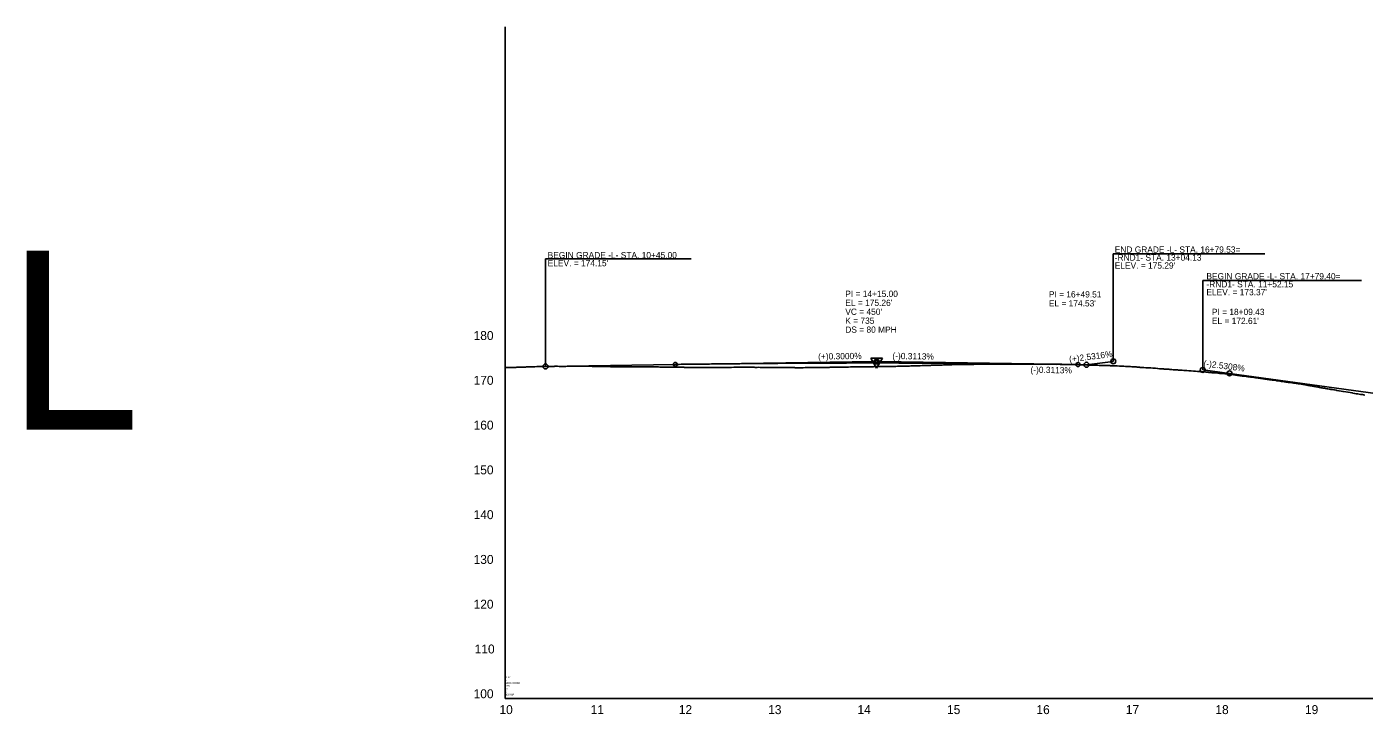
# Model space of a CAD drawing. Extents: x 1778432 to 1784301, y 601022 to 621789.
# Drawn here: x 1779608 to 1781103, y 621022 to 621789 of the extents above; entities that cross this region are included whole.
import ezdxf

# ---------------------------------------------------------------- set-up
doc = ezdxf.new("R2010")
doc.units = 0
for name, color, linetype in [('Exist Profile Cell', 7, 'Continuous'), ('Exist Vertical Profile Ground Line', 7, 'Continuous'), ('Exist Vertical Profile Horizontal Axis Label Major', 7, 'Continuous'), ('Exist Vertical Profile Vertical Axis Label', 7, 'Continuous'), ('Prop PFL Text', 7, 'Continuous'), ('Prop PFL VPI Symbol CELL', 7, 'Continuous'), ('Prop Vertical Profile Curve Label', 7, 'Continuous'), ('Prop Vertical Profile Grade', 7, 'Continuous'), ('Prop Vertical Profile Grade Label', 7, 'Continuous'), ('Prop VPI Label', 7, 'Continuous')]:
    doc.layers.add(name, color=color, linetype=linetype)

msp = doc.modelspace()

# ---------------------------------------------------------------- linework, layer by layer
at = {"layer": 'Exist Profile Cell'}
for q in [(1780143, 621789.2), (1784155.7, 621039.2), (1780143, 621039.2)]:
    msp.add_line((1780143, 621039.2), q, dxfattribs=at)
at = {"layer": 'Exist Vertical Profile Ground Line'}
msp.add_lwpolyline([(1780143, 621408.5), (1780143.6, 621408.6), (1780144.9, 621408.7), (1780145.6, 621408.7), (1780148.1, 621408.8), (1780150.2, 621408.8), (1780150.6, 621408.8), (1780151, 621408.8), (1780153.1, 621408.9), (1780155, 621408.9), (1780155.6, 621409), (1780156.3, 621409), (1780158.1, 621409), (1780158.9, 621409), (1780160.6, 621409.1), (1780162.1, 621409.1), (1780163.1, 621409.1), (1780164.3, 621409.2), (1780165.6, 621409.2), (1780166.8, 621409.3), (1780168.1, 621409.3), (1780169.2, 621409.3), (1780170.6, 621409.4), (1780172.3, 621409.5), (1780173.1, 621409.5), (1780173.9, 621409.5), (1780175.6, 621409.6), (1780176.2, 621409.6), (1780178.1, 621409.7), (1780180.2, 621409.7), (1780180.6, 621409.8), (1780183.3, 621409.8), (1780185.7, 621409.9), (1780186.9, 621409.9), (1780188.1, 621409.9), (1780190.9, 621410), (1780193.1, 621410), (1780195.2, 621410), (1780195.7, 621410), (1780197.5, 621410), (1780198.2, 621410.1), (1780199.9, 621410.1), (1780200.7, 621410.1), (1780201.5, 621410.1), (1780203.2, 621410), (1780204.2, 621410), (1780205.7, 621410), (1780207, 621410), (1780208.2, 621410), (1780209.4, 621410), (1780210.7, 621410), (1780212.2, 621410.1), (1780213.2, 621410.1), (1780214.8, 621410.1), (1780215.7, 621410.1), (1780217.5, 621410.2), (1780218.2, 621410.2), (1780218.8, 621410.2), (1780220.7, 621410.2), (1780221.2, 621410.2), (1780223.2, 621410.2), (1780223.5, 621410.2), (1780225.7, 621410.2), (1780228.2, 621410.2), (1780229.5, 621410.2), (1780230.8, 621410.2), (1780231.1, 621410.2), (1780232.7, 621410.1), (1780233.5, 621410.1), (1780235.7, 621410.1), (1780237.7, 621410.1), (1780238.2, 621410.1), (1780240.1, 621410), (1780240.7, 621410), (1780242.5, 621410), (1780243.2, 621410), (1780244.1, 621410), (1780245.7, 621409.9), (1780246.8, 621409.9), (1780248.2, 621409.9), (1780249.6, 621409.9), (1780250.8, 621409.9), (1780251.9, 621409.9), (1780253.3, 621409.8), (1780254.7, 621409.8), (1780255.8, 621409.7), (1780257.4, 621409.7), (1780258.3, 621409.7), (1780260.1, 621409.7), (1780260.8, 621409.6), (1780262.7, 621409.6), (1780263.3, 621409.6), (1780263.7, 621409.6), (1780265.8, 621409.6), (1780266.1, 621409.6), (1780268.5, 621409.6), (1780270.8, 621409.5), (1780271.7, 621409.5), (1780273.3, 621409.5), (1780275.8, 621409.5), (1780277.9, 621409.4), (1780278.3, 621409.4), (1780280.3, 621409.4), (1780280.8, 621409.4), (1780281.4, 621409.4), (1780283.3, 621409.4), (1780285, 621409.3), (1780285.8, 621409.3), (1780287.4, 621409.3), (1780288.3, 621409.3), (1780289.8, 621409.3), (1780290.8, 621409.3), (1780292, 621409.3), (1780293.3, 621409.3), (1780294.5, 621409.3), (1780295.8, 621409.3), (1780296.9, 621409.3), (1780298.3, 621409.3), (1780299.2, 621409.3), (1780300.8, 621409.3), (1780302.7, 621409.3), (1780303.3, 621409.3), (1780305.3, 621409.3), (1780305.8, 621409.3), (1780308, 621409.3), (1780308.3, 621409.3), (1780308.7, 621409.3), (1780310.9, 621409.3), (1780313.4, 621409.3), (1780314.2, 621409.3), (1780315.9, 621409.2), (1780318.4, 621409.2), (1780320.5, 621409.2), (1780320.9, 621409.2), (1780321.3, 621409.2), (1780323.4, 621409.2), (1780323.9, 621409.2), (1780325.9, 621409.1), (1780326.6, 621409.1), (1780328.4, 621409.1), (1780329.9, 621409.1), (1780330.9, 621409.1), (1780332.3, 621409.1), (1780333.4, 621409.1), (1780334.7, 621409), (1780335.9, 621409), (1780337.1, 621409), (1780338.4, 621409), (1780339.4, 621409), (1780340.9, 621409), (1780342.6, 621409), (1780343.4, 621408.9), (1780344.2, 621408.9), (1780345.9, 621408.9), (1780346.5, 621408.9), (1780348.4, 621408.9), (1780348.9, 621408.9), (1780350.9, 621408.9), (1780353.4, 621408.9), (1780356, 621408.9), (1780356.5, 621408.9), (1780358.6, 621408.9), (1780361.2, 621408.8), (1780363.4, 621408.8), (1780363.9, 621408.8), (1780366, 621408.9), (1780366.5, 621408.9), (1780368.5, 621408.8), (1780370.2, 621408.8), (1780371, 621408.8), (1780372.5, 621408.8), (1780373.5, 621408.8), (1780374.9, 621408.8), (1780376, 621408.8), (1780377.3, 621408.8), (1780378.5, 621408.8), (1780379.6, 621408.8), (1780381, 621408.9), (1780382.5, 621408.9), (1780383.5, 621408.9), (1780385.2, 621408.8), (1780386, 621408.8), (1780386.7, 621408.8), (1780388.5, 621408.9), (1780390.5, 621408.9), (1780391, 621408.9), (1780393.2, 621408.9), (1780393.5, 621408.9), (1780396, 621408.9), (1780398.5, 621409), (1780399.1, 621409), (1780401, 621409), (1780403.5, 621409), (1780405.6, 621409), (1780406, 621409), (1780408, 621409), (1780408.5, 621409), (1780409.1, 621409), (1780411, 621409), (1780412.7, 621409), (1780413.5, 621409), (1780415.1, 621409), (1780416, 621409), (1780417.5, 621409), (1780418.5, 621409), (1780419.8, 621409), (1780421, 621409), (1780422.2, 621408.9), (1780423.5, 621408.9), (1780424.6, 621408.9), (1780426.1, 621409), (1780427.7, 621408.9), (1780428.6, 621408.9), (1780430.4, 621408.9), (1780431.1, 621408.9), (1780431.6, 621408.9), (1780433.6, 621408.9), (1780434, 621408.9), (1780436.1, 621408.9), (1780436.4, 621408.9), (1780438.6, 621408.9), (1780441.1, 621408.9), (1780441.8, 621408.9), (1780443.6, 621408.9), (1780446.4, 621408.9), (1780448.6, 621408.8), (1780450.6, 621408.8), (1780451.1, 621408.8), (1780451.7, 621408.8), (1780453.6, 621408.7), (1780455.3, 621408.7), (1780456.1, 621408.7), (1780457.7, 621408.7), (1780458.6, 621408.7), (1780459.7, 621408.6), (1780461.1, 621408.6), (1780462.3, 621408.6), (1780463.6, 621408.6), (1780465, 621408.6), (1780466.1, 621408.6), (1780467.1, 621408.5), (1780468.6, 621408.5), (1780469.5, 621408.5), (1780471.1, 621408.5), (1780473, 621408.5), (1780473.6, 621408.5), (1780474.2, 621408.5), (1780476.1, 621408.5), (1780478.3, 621408.6), (1780478.6, 621408.6), (1780479, 621408.6), (1780481.3, 621408.6), (1780483.7, 621408.6), (1780484.5, 621408.6), (1780486.3, 621408.7), (1780488.7, 621408.7), (1780490.8, 621408.7), (1780491.2, 621408.7), (1780491.6, 621408.7), (1780493.7, 621408.7), (1780495.5, 621408.8), (1780496.2, 621408.8), (1780496.9, 621408.8), (1780498.7, 621408.8), (1780500.2, 621408.9), (1780501.2, 621408.9), (1780502.2, 621408.9), (1780503.7, 621408.9), (1780504.9, 621408.9), (1780506.2, 621409), (1780507.3, 621409), (1780508.7, 621409), (1780509.7, 621409), (1780511.2, 621409), (1780512.9, 621409), (1780513.7, 621409), (1780514.4, 621409), (1780516.2, 621409.1), (1780518.2, 621409.1), (1780518.7, 621409.1), (1780520.9, 621409.1), (1780521.5, 621409.1), (1780523.7, 621409.2), (1780526.5, 621409.2), (1780528.9, 621409.3), (1780531.2, 621409.3), (1780533.3, 621409.3), (1780533.7, 621409.3), (1780535.7, 621409.3), (1780536.2, 621409.3), (1780538.1, 621409.4), (1780538.8, 621409.4), (1780540.4, 621409.4), (1780541.3, 621409.4), (1780542.8, 621409.4), (1780543.8, 621409.4), (1780545.2, 621409.4), (1780546.3, 621409.5), (1780547.5, 621409.5), (1780548.8, 621409.5), (1780549.9, 621409.5), (1780551.3, 621409.5), (1780552.3, 621409.5), (1780553.8, 621409.6), (1780554.6, 621409.6), (1780556.3, 621409.7), (1780557, 621409.7), (1780558.8, 621409.7), (1780559.4, 621409.7), (1780561.3, 621409.7), (1780561.7, 621409.7), (1780563.8, 621409.8), (1780566.5, 621409.8), (1780568.8, 621409.8), (1780569.3, 621409.9), (1780571.3, 621409.9), (1780574.1, 621410), (1780576.3, 621410), (1780576.8, 621410), (1780578.8, 621410), (1780579.4, 621410), (1780581.3, 621410.1), (1780582.1, 621410.1), (1780583.8, 621410.1), (1780584.7, 621410.1), (1780586.3, 621410.2), (1780587.4, 621410.2), (1780588.8, 621410.2), (1780590.1, 621410.2), (1780591.3, 621410.3), (1780592.5, 621410.3), (1780593.8, 621410.3), (1780594.8, 621410.3), (1780596.3, 621410.4), (1780597.2, 621410.4), (1780598.8, 621410.5), (1780599.6, 621410.5), (1780601.4, 621410.5), (1780601.9, 621410.5), (1780603.9, 621410.6), (1780604.3, 621410.6), (1780606.7, 621410.7), (1780609, 621410.8), (1780611.4, 621410.9), (1780611.7, 621410.9), (1780614, 621411), (1780616.4, 621411.1), (1780618.5, 621411.1), (1780618.9, 621411.2), (1780619.3, 621411.2), (1780621.4, 621411.2), (1780622, 621411.3), (1780623.9, 621411.3), (1780624.7, 621411.3), (1780626.4, 621411.4), (1780627.9, 621411.4), (1780628.9, 621411.4), (1780630.3, 621411.5), (1780631.4, 621411.5), (1780632.7, 621411.6), (1780633.9, 621411.6), (1780635, 621411.7), (1780636.4, 621411.7), (1780637.4, 621411.7), (1780638.9, 621411.8), (1780640.6, 621411.8), (1780641.4, 621411.8), (1780642.1, 621411.8), (1780643.9, 621411.9), (1780644.5, 621411.9), (1780646.4, 621411.9), (1780646.9, 621411.9), (1780649.2, 621412), (1780651.6, 621412.1), (1780654.2, 621412.1), (1780656.5, 621412.1), (1780659, 621412.2), (1780661.1, 621412.2), (1780661.5, 621412.2), (1780661.9, 621412.2), (1780664, 621412.2), (1780665.8, 621412.2), (1780666.5, 621412.2), (1780668.2, 621412.3), (1780669, 621412.3), (1780670.5, 621412.3), (1780671.5, 621412.3), (1780672.9, 621412.3), (1780674, 621412.4), (1780675.2, 621412.4), (1780676.5, 621412.4), (1780677.6, 621412.4), (1780679, 621412.4), (1780680, 621412.4), (1780681.5, 621412.4), (1780682.3, 621412.4), (1780684, 621412.4), (1780684.7, 621412.4), (1780686.5, 621412.4), (1780687.1, 621412.4), (1780689, 621412.4), (1780689.4, 621412.4), (1780691.8, 621412.5), (1780694.2, 621412.4), (1780696.8, 621412.4), (1780699, 621412.5), (1780701.5, 621412.4), (1780703.6, 621412.4), (1780704, 621412.4), (1780706, 621412.3), (1780706.5, 621412.3), (1780708.4, 621412.3), (1780709, 621412.3), (1780710.7, 621412.3), (1780711.5, 621412.3), (1780713.1, 621412.3), (1780714.1, 621412.3), (1780715.5, 621412.3), (1780716.6, 621412.3), (1780717.8, 621412.3), (1780719.1, 621412.3), (1780720.2, 621412.3), (1780721.6, 621412.3), (1780723.1, 621412.4), (1780724.1, 621412.4), (1780724.9, 621412.4), (1780726.6, 621412.4), (1780728.4, 621412.5), (1780729.1, 621412.5), (1780731.1, 621412.5), (1780731.6, 621412.5), (1780733.8, 621412.6), (1780734.1, 621412.6), (1780736.6, 621412.6), (1780739.2, 621412.6), (1780741.6, 621412.6), (1780744.1, 621412.5), (1780746.2, 621412.4), (1780746.6, 621412.4), (1780748.6, 621412.4), (1780749.1, 621412.4), (1780749.7, 621412.4), (1780751.6, 621412.4), (1780752.4, 621412.4), (1780754.1, 621412.3), (1780755.6, 621412.3), (1780756.6, 621412.3), (1780757.7, 621412.3), (1780759.1, 621412.2), (1780760.4, 621412.3), (1780761.6, 621412.3), (1780763.1, 621412.2), (1780764.1, 621412.2), (1780765.7, 621412.2), (1780766.6, 621412.1), (1780768.4, 621412.1), (1780769.2, 621412.1), (1780769.8, 621412.1), (1780771.7, 621412), (1780772.2, 621412), (1780774.2, 621412), (1780774.6, 621412), (1780776.9, 621412), (1780779.3, 621411.9), (1780781.3, 621411.9), (1780781.7, 621411.9), (1780784.2, 621411.8), (1780786.7, 621411.7), (1780788.8, 621411.7), (1780789.2, 621411.7), (1780791.1, 621411.6), (1780791.7, 621411.6), (1780793.5, 621411.5), (1780794.2, 621411.5), (1780795.8, 621411.5), (1780796.7, 621411.4), (1780798.2, 621411.4), (1780799.2, 621411.4), (1780800.6, 621411.3), (1780801.7, 621411.3), (1780803, 621411.3), (1780804.2, 621411.2), (1780805.3, 621411.2), (1780806.7, 621411.1), (1780807.7, 621411.1), (1780809.2, 621411.1), (1780810.1, 621411), (1780811.7, 621411), (1780812.4, 621411), (1780814.2, 621410.9), (1780814.8, 621410.9), (1780816.7, 621410.8), (1780818.9, 621410.8), (1780819.2, 621410.7), (1780821.7, 621410.7), (1780824.3, 621410.6), (1780826.9, 621410.5), (1780829.3, 621410.3), (1780829.6, 621410.3), (1780831.8, 621410.2), (1780833.7, 621410.1), (1780834.3, 621410.1), (1780836, 621410), (1780836.8, 621410), (1780837.6, 621409.9), (1780839.3, 621409.9), (1780840.8, 621409.8), (1780841.8, 621409.7), (1780843.1, 621409.6), (1780844.3, 621409.5), (1780845.5, 621409.4), (1780846.8, 621409.3), (1780847.9, 621409.3), (1780849.3, 621409.2), (1780850.3, 621409.1), (1780851.8, 621409), (1780852.6, 621408.9), (1780854.3, 621408.8), (1780856.2, 621408.7), (1780856.8, 621408.7), (1780858.9, 621408.5), (1780859.3, 621408.5), (1780862.1, 621408.3), (1780864.4, 621408.2), (1780866.8, 621408), (1780869.5, 621407.9), (1780871.8, 621407.7), (1780872.2, 621407.6), (1780874.3, 621407.4), (1780876.3, 621407.3), (1780876.8, 621407.2), (1780878.6, 621407.1), (1780879.3, 621407), (1780880.1, 621407), (1780881.8, 621406.8), (1780882.8, 621406.8), (1780884.4, 621406.7), (1780885.7, 621406.6), (1780886.9, 621406.5), (1780888.1, 621406.4), (1780889.4, 621406.3), (1780890.8, 621406.2), (1780891.9, 621406.2), (1780893.5, 621406.1), (1780894.4, 621406), (1780895.2, 621405.9), (1780896.9, 621405.8), (1780897.6, 621405.8), (1780899.4, 621405.6), (1780901.4, 621405.5), (1780901.9, 621405.5), (1780904.6, 621405.3), (1780907, 621405.1), (1780909.1, 621404.9), (1780909.4, 621404.9), (1780912.1, 621404.7), (1780914.4, 621404.5), (1780916.5, 621404.3), (1780916.9, 621404.3), (1780918.8, 621404.1), (1780919.4, 621404.1), (1780921.2, 621404), (1780921.9, 621403.9), (1780922.7, 621403.8), (1780924.4, 621403.7), (1780925.9, 621403.5), (1780926.9, 621403.4), (1780928, 621403.4), (1780929.4, 621403.3), (1780930.7, 621403.1), (1780931.9, 621403), (1780933, 621402.9), (1780934.4, 621402.8), (1780936, 621402.7), (1780936.9, 621402.6), (1780937.8, 621402.6), (1780939.4, 621402.4), (1780941.3, 621402.2), (1780942, 621402.1), (1780942.5, 621402.1), (1780944.5, 621401.9), (1780947, 621401.6), (1780949.6, 621401.4), (1780951.5, 621401.1), (1780952, 621401.1), (1780954.5, 621400.8), (1780956.7, 621400.5), (1780957, 621400.5), (1780959, 621400.2), (1780959.5, 621400.2), (1780961.4, 621399.8), (1780962, 621399.7), (1780963.8, 621399.5), (1780964.5, 621399.4), (1780966.1, 621399.3), (1780967, 621399.2), (1780968.5, 621399), (1780969.5, 621398.9), (1780970.9, 621398.7), (1780972, 621398.6), (1780973.2, 621398.4), (1780974.5, 621398.2), (1780975.9, 621398), (1780977, 621397.9), (1780978, 621397.8), (1780979.5, 621397.6), (1780981.3, 621397.3), (1780982, 621397.2), (1780983.9, 621397), (1780984.5, 621396.9), (1780985, 621396.8), (1780987, 621396.5), (1780989.5, 621396.2), (1780992, 621395.8), (1780994.1, 621395.6), (1780994.5, 621395.5), (1780997.2, 621395.1), (1780999.6, 621394.8), (1780999.9, 621394.7), (1781002.1, 621394.4), (1781004, 621394.2), (1781004.6, 621394.1), (1781005.2, 621394), (1781007.1, 621393.7), (1781008.7, 621393.5), (1781009.6, 621393.3), (1781010.5, 621393.2), (1781012.1, 621393), (1781013.4, 621392.8), (1781014.6, 621392.6), (1781015.8, 621392.5), (1781017.1, 621392.3), (1781018.5, 621392.1), (1781019.6, 621391.9), (1781020.5, 621391.8), (1781022.1, 621391.6), (1781023.8, 621391.3), (1781024.6, 621391.2), (1781025.3, 621391.1), (1781027.1, 621390.8), (1781029.2, 621390.5), (1781029.6, 621390.4), (1781030, 621390.3), (1781032.4, 621390), (1781034.6, 621389.6), (1781036.5, 621389.3), (1781037.1, 621389.2), (1781039.8, 621388.7), (1781042.1, 621388.4), (1781042.5, 621388.3), (1781044.6, 621387.9), (1781046.5, 621387.6), (1781047.1, 621387.5), (1781048.9, 621387.1), (1781049.6, 621387), (1781051.3, 621386.7), (1781052.1, 621386.6), (1781053.1, 621386.4), (1781054.6, 621386.1), (1781055.8, 621386), (1781057.2, 621385.7), (1781058.5, 621385.5), (1781059.7, 621385.3), (1781061.1, 621385), (1781062.2, 621384.8), (1781063.8, 621384.6), (1781064.7, 621384.4), (1781065.5, 621384.3), (1781067.2, 621384.1), (1781069.1, 621383.7), (1781069.7, 621383.6), (1781071.7, 621383.3), (1781072.2, 621383.2), (1781072.6, 621383.1), (1781074.7, 621382.8), (1781077.3, 621382.3), (1781079, 621382.1), (1781079.7, 621381.9), (1781082.4, 621381.5), (1781084.7, 621381.1), (1781085, 621381.1), (1781087.2, 621380.7), (1781089.1, 621380.3), (1781089.7, 621380.3), (1781090.4, 621380.1), (1781092.2, 621379.8), (1781093.8, 621379.5), (1781094.7, 621379.4), (1781095.7, 621379.2), (1781097.2, 621379), (1781098.6, 621378.7), (1781099.7, 621378.6), (1781100.9, 621378.4), (1781102.2, 621378.2), (1781103.7, 621378)], dxfattribs=at)
at = {"layer": 'Prop PFL VPI Symbol CELL'}
for p, q in [((1780558, 621408), (1780551.5, 621419.2)), ((1780564.4, 621419.2), (1780551.5, 621419.2)), ((1780558, 621408), (1780564.4, 621419.2))]:
    msp.add_line(p, q, dxfattribs=at)
for radius in [1.75, 1.2]:
    msp.add_circle((1780558, 621415.5), radius, dxfattribs=at)
at = {"layer": 'Prop Vertical Profile Curve Label'}
for centre in [(1780333, 621412.1), (1780783, 621412)]:
    msp.add_circle(centre, 2.25, dxfattribs=at)
at = {"layer": 'Prop Vertical Profile Grade'}
for p, q in [((1780188, 621409.9), (1780333, 621412.1)), ((1780783, 621412), (1780792.5, 621411.8)), ((1780792.5, 621411.8), (1780822.5, 621415.6)), ((1780922.4, 621406), (1780952.4, 621402.2)), ((1780952.4, 621402.2), (1781118, 621379.4))]:
    msp.add_line(p, q, dxfattribs=at)
msp.add_spline([(1780333, 621412.1), (1780342, 621412.3), (1780351, 621412.4), (1780360, 621412.5), (1780369, 621412.6), (1780378, 621412.7), (1780387, 621412.8), (1780396, 621412.9), (1780405, 621413), (1780414, 621413.1), (1780423, 621413.2), (1780432, 621413.3), (1780441, 621413.3), (1780450, 621413.4), (1780459, 621413.5), (1780468, 621413.5), (1780477, 621413.6), (1780486, 621413.6), (1780495, 621413.7), (1780504, 621413.7), (1780513, 621413.7), (1780522, 621413.7), (1780531, 621413.8), (1780540, 621413.8), (1780549, 621413.8), (1780558, 621413.8), (1780567, 621413.8), (1780576, 621413.8), (1780585, 621413.7), (1780594, 621413.7), (1780603, 621413.7), (1780612, 621413.7), (1780621, 621413.6), (1780630, 621413.6), (1780639, 621413.5), (1780648, 621413.5), (1780657, 621413.4), (1780666, 621413.3), (1780675, 621413.3), (1780684, 621413.2), (1780693, 621413.1), (1780702, 621413), (1780711, 621412.9), (1780720, 621412.8), (1780729, 621412.7), (1780738, 621412.6), (1780747, 621412.5), (1780756, 621412.4), (1780765, 621412.3), (1780774, 621412.1), (1780783, 621412)], degree=3, dxfattribs=at)
at = {"layer": 'Prop VPI Label'}
for p, q in [((1780188, 621409.9), (1780188, 621529.9)), ((1780188, 621529.9), (1780350.8, 621529.9)), ((1780822.5, 621415.6), (1780822.5, 621535.6)), ((1780822.5, 621535.6), (1780991.7, 621535.6)), ((1780922.4, 621406), (1780922.4, 621506)), ((1780922.4, 621506), (1781099.9, 621506)), ((1780333, 621412.1), (1780555.2, 621415.5)), ((1780783, 621412), (1780560.7, 621415.5))]:
    msp.add_line(p, q, dxfattribs=at)
for centre in [(1780188, 621409.9), (1780558, 621415.5), (1780792.5, 621411.8), (1780822.5, 621415.6), (1780922.4, 621406), (1780952.4, 621402.2)]:
    msp.add_circle(centre, 2.75, dxfattribs=at)

# ---------------------------------------------------------------- texts
at = {"layer": 'Exist Profile Cell'}
for s, p in [('RDY', (1780143, 621061.9)), ('2', (1780143, 621045.7)), ('L', (1780143, 621058.7)), ('1000.000000', (1780143, 621055.4)), ('100', (1780143, 621052.2)), ('10', (1780143, 621048.9)), ('NOGAP', (1780143, 621042.4))]:
    msp.add_text(s, height=2, dxfattribs=at).set_placement(p)
at = {"layer": 'Exist Vertical Profile Horizontal Axis Label Major'}
for s, p in [('10', (1780136.5, 621021.7)), ('10', (1780136.5, 621021.7)), ('11', (1780238.4, 621021.7)), ('11', (1780238.4, 621021.7)), ('12', (1780336.9, 621021.7)), ('12', (1780336.9, 621021.7)), ('13', (1780436.8, 621021.7)), ('13', (1780436.8, 621021.7)), ('14', (1780536.6, 621021.7)), ('15', (1780636.7, 621021.7)), ('16', (1780736.6, 621021.7)), ('17', (1780836.5, 621021.7)), ('18', (1780936.6, 621021.7)), ('19', (1781036.7, 621021.7))]:
    msp.add_text(s, height=10, dxfattribs=at).set_placement(p)
at = {"layer": 'Exist Vertical Profile Vertical Axis Label'}
for s, p in [('180', (1780107.6, 621439.4)), ('180', (1780107.6, 621439.4)), ('170', (1780107.6, 621389.4)), ('170', (1780107.6, 621389.4)), ('160', (1780107.6, 621339.4)), ('160', (1780107.6, 621339.4)), ('150', (1780107.6, 621289.4)), ('150', (1780107.6, 621289.4)), ('140', (1780107.6, 621239.4)), ('140', (1780107.6, 621239.4)), ('130', (1780107.6, 621189.4)), ('130', (1780107.6, 621189.4)), ('120', (1780107.6, 621139.4)), ('120', (1780107.6, 621139.4)), ('110', (1780108.8, 621089.4)), ('110', (1780108.8, 621089.4)), ('100', (1780107.6, 621039.4)), ('100', (1780107.6, 621039.4))]:
    msp.add_text(s, height=10, dxfattribs=at).set_placement(p)
at = {"layer": 'Prop PFL Text'}
msp.add_text('L', height=200, dxfattribs=at).set_placement((1779586.3, 621339.2))
at = {"layer": 'Prop Vertical Profile Curve Label'}
for s, p in [("VC = 450'", (1780523, 621467.5)), ('K = 735', (1780523, 621457.5)), ('DS = 80 MPH', (1780523, 621447.5))]:
    msp.add_text(s, height=7, dxfattribs=at).set_placement(p)
at = {"layer": 'Prop Vertical Profile Grade Label'}
for s, rotation, p in [('(+)0.3000%', 0.8594, (1780492.7, 621417.5)), ('(-)0.3113%', 359.1065, (1780575.6, 621418.2)), ('(+)2.5316%', 7.218, (1780773.6, 621414.4)), ('(-)0.3113%', 359.1065, (1780729.9, 621402.8)), ('(-)2.5308%', 352.821, (1780923, 621410))]:
    msp.add_text(s, height=7, rotation=rotation, dxfattribs=at).set_placement(p)
at = {"layer": 'Prop VPI Label'}
for s, p in [('END GRADE -L- STA. 16+79.53=', (1780824.1, 621536.9)), ('BEGIN GRADE -L- STA. 10+45.00', (1780190.4, 621530.7)), ("ELEV. = 174.15'", (1780190.4, 621521.8)), ('-RND1- STA. 13+04.13', (1780824.1, 621528)), ("ELEV. = 175.29'", (1780824.1, 621519.1)), ('BEGIN GRADE -L- STA. 17+79.40=', (1780926.6, 621507.1)), ('-RND1- STA. 11+52.15', (1780926.6, 621498.2)), ("ELEV. = 173.37'", (1780926.6, 621489.4)), ('PI = 14+15.00', (1780523, 621487.5)), ("EL = 175.26'", (1780523, 621477.5)), ('PI = 16+49.51', (1780750.5, 621486.9)), ("EL = 174.53'", (1780750.5, 621476.9)), ('PI = 18+09.43', (1780932.7, 621467.3)), ("EL = 172.61'", (1780932.7, 621457.3))]:
    msp.add_text(s, height=7, dxfattribs=at).set_placement(p)

doc.saveas('drawing.dxf')
